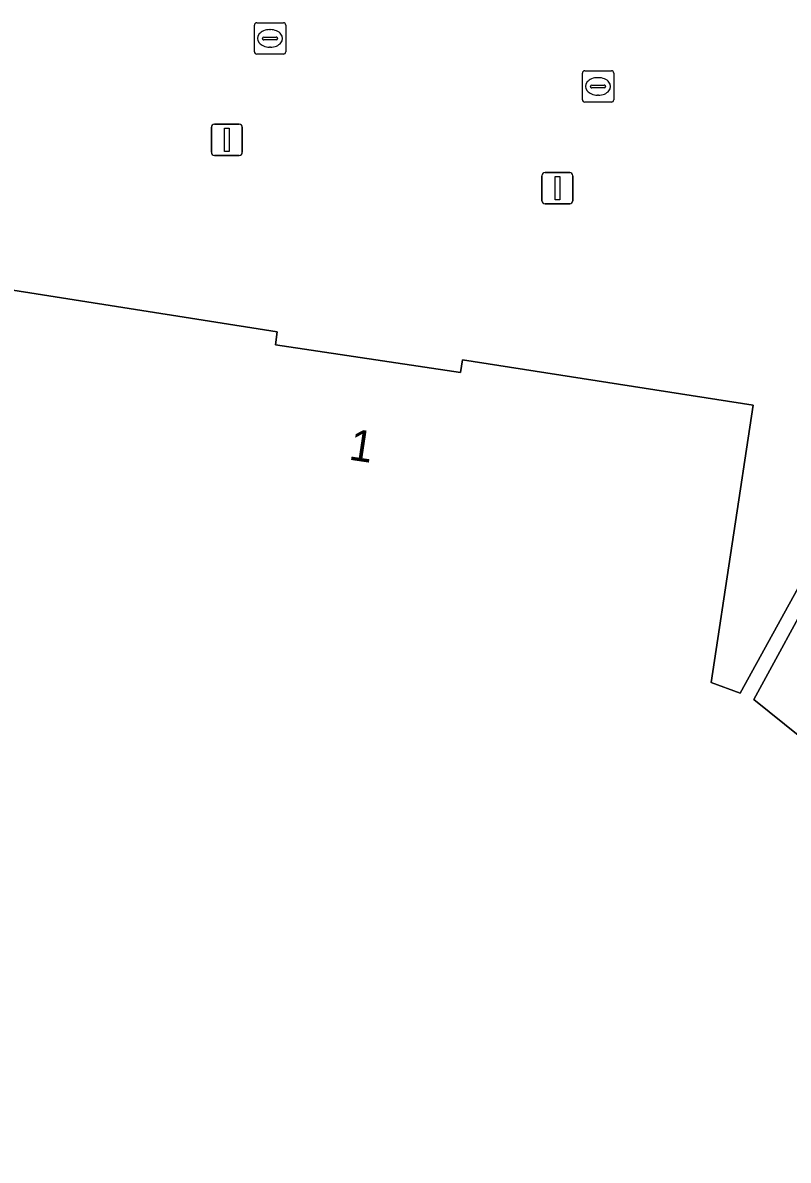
# Model space of a CAD drawing. Extents: x 161090 to 161692, y 379509 to 380907.
# Drawn here: x 161535.21 to 161559.69, y 380394.7 to 380431.06 of the extents above; entities that cross this region are included whole.
import ezdxf

# ---------------------------------------------------------------- set-up
doc = ezdxf.new("R2010")
doc.units = 0
for name, color, linetype in [('IMGEO_Kolk', 7, 'Continuous'), ('IMGEO_Lichtmast', 7, 'Continuous'), ('IMGEO_Pand', 7, 'Continuous'), ('IMGEO_Pand_nummerreeks', 7, 'Continuous'), ('IMGEO_Voetpad_open', 7, 'Continuous')]:
    doc.layers.add(name, color=color, linetype=linetype)

msp = doc.modelspace()

# ---------------------------------------------------------------- linework, layer by layer
at = {"layer": 'IMGEO_Kolk'}
for p, q in [((161542.621, 380430.138), (161542.621, 380430.99)), ((161542.696, 380431.064), (161543.548, 380431.064)), ((161543.622, 380430.99), (161543.622, 380430.138)), ((161542.88, 380430.558), (161542.88, 380430.57)), ((161543.318, 380430.521), (161542.92, 380430.521)), ((161542.923, 380430.607), (161543.321, 380430.607)), ((161543.109, 380430.844), (161543.134, 380430.844)), ((161543.364, 380430.57), (161543.364, 380430.558)), ((161543.132, 380430.284), (161543.107, 380430.284)), ((161543.548, 380430.064), (161542.696, 380430.064)), ((161553.11, 380428.603), (161553.11, 380429.455)), ((161553.185, 380429.529), (161554.037, 380429.529)), ((161554.111, 380429.455), (161554.111, 380428.603)), ((161553.369, 380429.023), (161553.369, 380429.035)), ((161553.412, 380429.072), (161553.81, 380429.072)), ((161553.598, 380429.309), (161553.623, 380429.309)), ((161553.853, 380429.035), (161553.853, 380429.023)), ((161553.807, 380428.986), (161553.409, 380428.986)), ((161553.621, 380428.749), (161553.596, 380428.749)), ((161554.037, 380428.529), (161553.185, 380428.529))]:
    msp.add_line(p, q, dxfattribs=at)
for points in [[(161542.621, 380430.138), (161542.621, 380430.99)], [(161542.696, 380431.064), (161543.548, 380431.064)], [(161543.622, 380430.99), (161543.622, 380430.138)], [(161543.548, 380430.064), (161542.696, 380430.064)], [(161553.11, 380428.603), (161553.11, 380429.455)], [(161553.185, 380429.529), (161554.037, 380429.529)], [(161554.111, 380429.455), (161554.111, 380428.603)], [(161554.037, 380428.529), (161553.185, 380428.529)]]:
    msp.add_lwpolyline(points, dxfattribs=at)
for centre, radius, start, end in [((161542.698, 380430.988), 0.0765, 91.552, 178.448), ((161542.698, 380430.988), 0.0765, 91.552, 178.448), ((161543.546, 380430.988), 0.0765, 1.552, 88.448), ((161543.546, 380430.988), 0.0765, 1.552, 88.448), ((161542.92, 380430.567), 0.0403, 85.8775, 175.7526), ((161542.917, 380430.557), 0.0366, 178.938, 274.7102), ((161543.321, 380430.564), 0.043, 264.8664, 352.4533), ((161543.325, 380430.569), 0.0386, 1.7309, 96.639), ((161542.698, 380430.14), 0.0765, 181.552, 268.448), ((161542.698, 380430.14), 0.0765, 181.552, 268.448), ((161543.546, 380430.14), 0.0765, 271.552, 358.448), ((161543.546, 380430.14), 0.0765, 271.552, 358.448), ((161553.187, 380429.453), 0.0765, 91.552, 178.448), ((161553.187, 380429.453), 0.0765, 91.552, 178.448), ((161554.035, 380429.453), 0.0765, 1.552, 88.448), ((161554.035, 380429.453), 0.0765, 1.552, 88.448), ((161553.409, 380429.032), 0.0403, 85.8775, 175.7526), ((161553.814, 380429.034), 0.0386, 1.7309, 96.639), ((161553.406, 380429.022), 0.0366, 178.938, 274.7102), ((161553.81, 380429.029), 0.043, 264.8664, 352.4533), ((161553.187, 380428.605), 0.0765, 181.552, 268.448), ((161553.187, 380428.605), 0.0765, 181.552, 268.448), ((161554.035, 380428.605), 0.0765, 271.552, 358.448), ((161554.035, 380428.605), 0.0765, 271.552, 358.448)]:
    msp.add_arc(centre, radius, start, end, dxfattribs=at)
for centre, major_axis, ratio, start_param, end_param in [((161543.108, 380430.564), (-0.387, 0.002), 0.722429, 4.712389, 7.853982), ((161543.133, 380430.564), (-0.39, 0.002), 0.717154, 1.570796, 4.712389), ((161553.597, 380429.029), (-0.387, 0.002), 0.722429, 4.712389, 7.853982), ((161553.622, 380429.029), (-0.39, 0.002), 0.717154, 1.570796, 4.712389)]:
    msp.add_ellipse(centre, major_axis=major_axis, ratio=ratio, start_param=start_param, end_param=end_param, dxfattribs=at)
at = {"layer": 'IMGEO_Lichtmast'}
for p, q in [((161541.244, 380426.924), (161541.244, 380427.724)), ((161541.244, 380427.724), (161541.244, 380426.924)), ((161541.344, 380427.824), (161542.134, 380427.824)), ((161542.134, 380427.824), (161541.344, 380427.824)), ((161542.234, 380427.724), (161542.234, 380426.924)), ((161542.234, 380426.924), (161542.234, 380427.724)), ((161542.134, 380426.824), (161541.344, 380426.824)), ((161541.344, 380426.824), (161542.134, 380426.824)), ((161551.816, 380425.373), (161551.816, 380426.173)), ((161551.816, 380426.173), (161551.816, 380425.373)), ((161551.916, 380426.273), (161552.706, 380426.273)), ((161552.706, 380426.273), (161551.916, 380426.273)), ((161552.806, 380426.173), (161552.806, 380425.373)), ((161552.806, 380425.373), (161552.806, 380426.173)), ((161552.706, 380425.273), (161551.916, 380425.273)), ((161551.916, 380425.273), (161552.706, 380425.273))]:
    msp.add_line(p, q, dxfattribs=at)
for points in [[(161541.664, 380427.699), (161541.814, 380427.699), (161541.814, 380426.949), (161541.664, 380426.949), (161541.664, 380427.699)], [(161552.236, 380426.148), (161552.386, 380426.148), (161552.386, 380425.398), (161552.236, 380425.398), (161552.236, 380426.148)]]:
    msp.add_lwpolyline(points, dxfattribs=at)
for centre, start, end in [((161541.344, 380427.724), 90, 180), ((161541.344, 380427.724), 90, 180), ((161542.134, 380427.724), 0, 90), ((161542.134, 380427.724), 360, 90), ((161541.344, 380426.924), 180, 270), ((161541.344, 380426.924), 180, 270), ((161542.134, 380426.924), 270, 0), ((161542.134, 380426.924), 270, 0), ((161551.916, 380426.173), 90, 180), ((161551.916, 380426.173), 90, 180), ((161552.706, 380426.173), 0, 90), ((161552.706, 380426.173), 360, 90), ((161551.916, 380425.373), 180, 270), ((161551.916, 380425.373), 180, 270), ((161552.706, 380425.373), 270, 0), ((161552.706, 380425.373), 270, 0)]:
    msp.add_arc(centre, 0.1, start, end, dxfattribs=at)
at = {"layer": 'IMGEO_Pand'}
msp.add_lwpolyline([(161576.089, 380389.566), (161572.873, 380394.919), (161569.355, 380400.774), (161570.928, 380402.151), (161572.534, 380403.556), (161572.222, 380403.897), (161570.561, 380402.435), (161568.999, 380401.06), (161558.595, 380409.43), (161560.648, 380413.202), (161560.248, 380413.425), (161558.15, 380409.628), (161557.225, 380409.976), (161558.567, 380418.844), (161549.278, 380420.286), (161549.217, 380419.881), (161543.293, 380420.766), (161543.349, 380421.185), (161534.077, 380422.646)], dxfattribs=at)
at = {"layer": 'IMGEO_Voetpad_open'}
for points in [[(161534.077, 380422.646), (161543.349, 380421.185), (161543.293, 380420.766), (161549.217, 380419.881), (161549.278, 380420.286), (161558.567, 380418.844), (161557.225, 380409.976), (161558.15, 380409.628), (161560.248, 380413.425)], [(161560.648, 380413.202), (161558.595, 380409.43), (161568.999, 380401.06)]]:
    msp.add_lwpolyline(points, dxfattribs=at)

# ---------------------------------------------------------------- texts
at = {"layer": 'IMGEO_Pand_nummerreeks'}
msp.add_text('1', height=1, rotation=351.503, dxfattribs=at).set_placement((161545.611, 380417.103))

doc.saveas('drawing.dxf')
